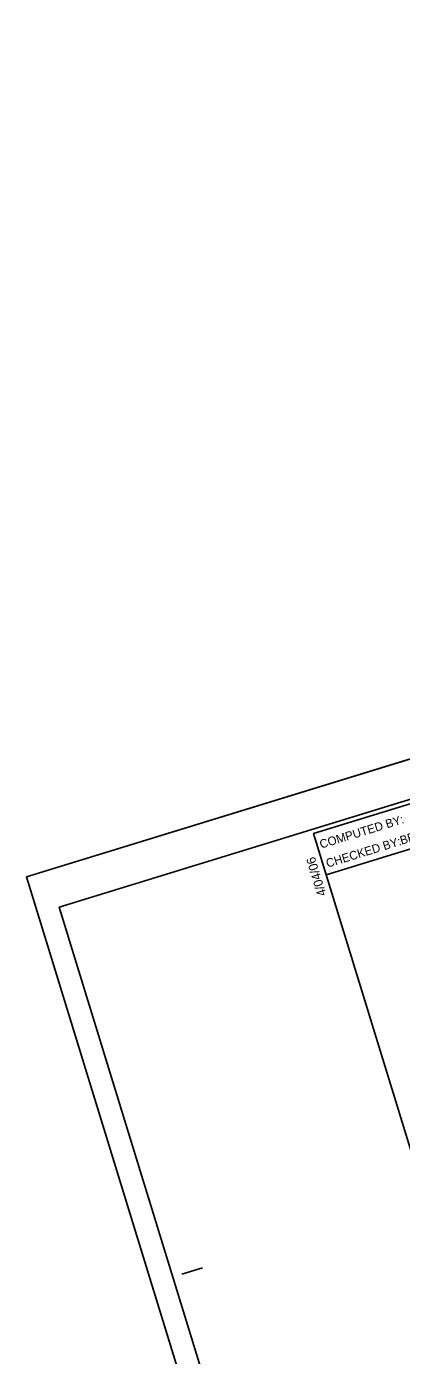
# Model space of a CAD drawing. Extents: x 2528815 to 2532488, y 739965 to 742287.
# Drawn here: x 2529859 to 2530077, y 741422 to 742195 of the extents above; entities that cross this region are included whole.
import ezdxf

# ---------------------------------------------------------------- set-up
doc = ezdxf.new("R2010")
doc.units = 0
for name, color, linetype in [('Sheet Cutting Line CELL', 7, 'Continuous'), ('Sheet Data Field CELL', 7, 'Continuous'), ('Sheet Plot Border Inside CELL', 7, 'Continuous'), ('Sheet Plot Border Outside CELL', 7, 'Continuous'), ('Sheet Summary Combination CELL', 7, 'Continuous')]:
    doc.layers.add(name, color=color, linetype=linetype)

msp = doc.modelspace()

# ---------------------------------------------------------------- linework, layer by layer
at = {"layer": 'Sheet Cutting Line CELL'}
for p, q in [((2531468.39, 742195.25), (2529858.69, 741700.56)), ((2529858.69, 741700.56), (2530181.83, 740649.09))]:
    msp.add_line(p, q, dxfattribs=at)
at = {"layer": 'Sheet Plot Border Inside CELL'}
msp.add_lwpolyline([(2531470.68, 742172.47), (2529877.71, 741682.92), (2530187.66, 740674.37), (2531780.63, 741163.93)], close=True, dxfattribs=at)
at = {"layer": 'Sheet Plot Border Outside CELL'}
msp.add_lwpolyline([(2531468.39, 742195.25), (2529858.69, 741700.56), (2530181.83, 740649.09), (2531791.53, 741143.79)], close=True, dxfattribs=at)
at = {"layer": 'Sheet Summary Combination CELL'}
msp.add_line((2529949.08, 741469.42), (2529961.03, 741473.09), dxfattribs=at)
for points in [[(2531459.48, 742166.36), (2530025.67, 741725.72), (2530334.11, 740722.05), (2531767.93, 741162.69)], [(2530025.67, 741725.72), (2530221.91, 741786.03), (2530229.25, 741762.13), (2530033.01, 741701.83)]]:
    msp.add_lwpolyline(points, close=True, dxfattribs=at)

# ---------------------------------------------------------------- texts
at = {"layer": 'Sheet Data Field CELL'}
msp.add_text('BEH                   ', height=5.0001, rotation=17.08323, dxfattribs=at).set_placement((2530076.83, 741719.22))
at = {"layer": 'Sheet Summary Combination CELL'}
for s, height, rotation, p in [('COMPUTED BY:', 5.0001, 17.08323, (2530030.08, 741716.98)), ('CHECKED BY:', 5.0001, 17.08323, (2530033.8, 741705.89)), ('4/04/06', 5.25, 107.08323, (2530033.2, 741690.26))]:
    msp.add_text(s, height=height, rotation=rotation, dxfattribs=at).set_placement(p)

doc.saveas('drawing.dxf')
